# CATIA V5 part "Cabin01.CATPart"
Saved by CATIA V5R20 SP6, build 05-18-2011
Part number: Cabin01
Bounding box of the stored display mesh (mm): x -71.5 to 71.5, y 0 to 20, z 20 to 260
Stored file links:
  E:\#01 CATIA Lecture Materials\#06 DMU\#01 DMU KIN Page01 EX01\#01 CATPart\Cabin01.CATPart
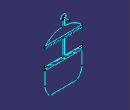
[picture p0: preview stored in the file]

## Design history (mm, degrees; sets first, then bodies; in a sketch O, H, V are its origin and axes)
Set1
  DatumCurve1 "Curve.1 ( *CRV3 - wsp *MASTER -  )"
  DatumCurve2 "Curve.2 ( *CRV4 - wsp *MASTER -  )"
  DatumCurve3 "Curve.3 ( *CRV5 - wsp *MASTER -  )"
  DatumCurve4 "Curve.4 ( *CRV6 - wsp *MASTER -  )"
  DatumCurve5 "Curve.5 ( *CRV7 - wsp *MASTER -  )"
  DatumCurve6 "Curve.6 ( *CRV8 - wsp *MASTER -  )"
  DatumCurve7 "Curve.7 ( *CRV9 - wsp *MASTER -  )"
  DatumCurve8 "Curve.8 ( *CRV10 - wsp *MASTER -  )"
  DatumCurve9 "Curve.9 ( *CRV11 - wsp *MASTER -  )"
  DatumCurve10 "Curve.10 ( *CRV12 - wsp *MASTER -  )"
  DatumCurve11 "Curve.11 ( *CRV13 - wsp *MASTER -  )"
  DatumCurve12 "Curve.12 ( *CRV14 - wsp *MASTER -  )"
  DatumCurve13 "Curve.13 ( *CRV15 - wsp *MASTER -  )"
  DatumCurve14 "Curve.14 ( *CRV16 - wsp *MASTER -  )"
  DatumCurve15 "Curve.15 ( *CRV17 - wsp *MASTER -  )"
  DatumCurve16 "Curve.16 ( *CRV18 - wsp *MASTER -  )"
  DatumCurve17 "Curve.17 ( *CRV19 - wsp *MASTER -  )"
  Line1 "Line.1 ( *LN23 - wsp *MASTER -  )": stored without definition
  Line2 "Line.2 ( *LN24 - wsp *MASTER -  )": stored without definition
  Line3 "Line.3 ( *LN25 - wsp *MASTER -  )": stored without definition
  Line4 "Line.4 ( *LN26 - wsp *MASTER -  )": stored without definition
  Line5 "Line.5 ( *LN27 - wsp *MASTER -  )": stored without definition
  Line6 "Line.6 ( *LN28 - wsp *MASTER -  )": stored without definition
  Line7 "Line.7 ( *LN29 - wsp *MASTER -  )": stored without definition
  Line8 "Line.8 ( *LN30 - wsp *MASTER -  )": stored without definition
  Line9 "Line.9 ( *LN31 - wsp *MASTER -  )": stored without definition
  Line10 "Line.10 ( *LN32 - wsp *MASTER -  )": stored without definition
  Line11 "Line.11 ( *LN33 - wsp *MASTER -  )": stored without definition
  Line12 "Line.12 ( *LN34 - wsp *MASTER -  )": stored without definition
  Line13 "Line.13 ( *LN35 - wsp *MASTER -  )": stored without definition
  Line14 "Line.14 ( *LN36 - wsp *MASTER -  )": stored without definition
  Line15 "Line.15 ( *LN37 - wsp *MASTER -  )": stored without definition
  Line16 "Line.16 ( *LN38 - wsp *MASTER -  )": stored without definition
  Line17 "Line.17 ( *LN39 - wsp *MASTER -  )": stored without definition
  Line18 "Line.18 ( *LN40 - wsp *MASTER -  )": stored without definition
  Line19 "Line.19 ( *LN41 - wsp *MASTER -  )": stored without definition
  Line20 "Line.20 ( *LN42 - wsp *MASTER -  )": stored without definition
  Line21 "Line.21 ( *LN43 - wsp *MASTER -  )": stored without definition
  Line22 "Line.22 ( *LN44 - wsp *MASTER -  )": stored without definition
  Line23 "Line.23 ( *LN45 - wsp *MASTER -  )": stored without definition
  Line24 "Line.24 ( *LN46 - wsp *MASTER -  )": stored without definition
  Line25 "Line.25 ( *LN47 - wsp *MASTER -  )": stored without definition
  Line26 "Line.26 ( *LN48 - wsp *MASTER -  )": stored without definition
  Line27 "Line.27 ( *LN49 - wsp *MASTER -  )": stored without definition
  Line28 "Line.28 ( *LN50 - wsp *MASTER -  )": stored without definition
  Line29 "Line.29 ( *LN51 - wsp *MASTER -  )": stored without definition
  Line30 "Line.30 ( *LN52 - wsp *MASTER -  )": stored without definition
  Line31: stored without definition
Body1 (main body)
